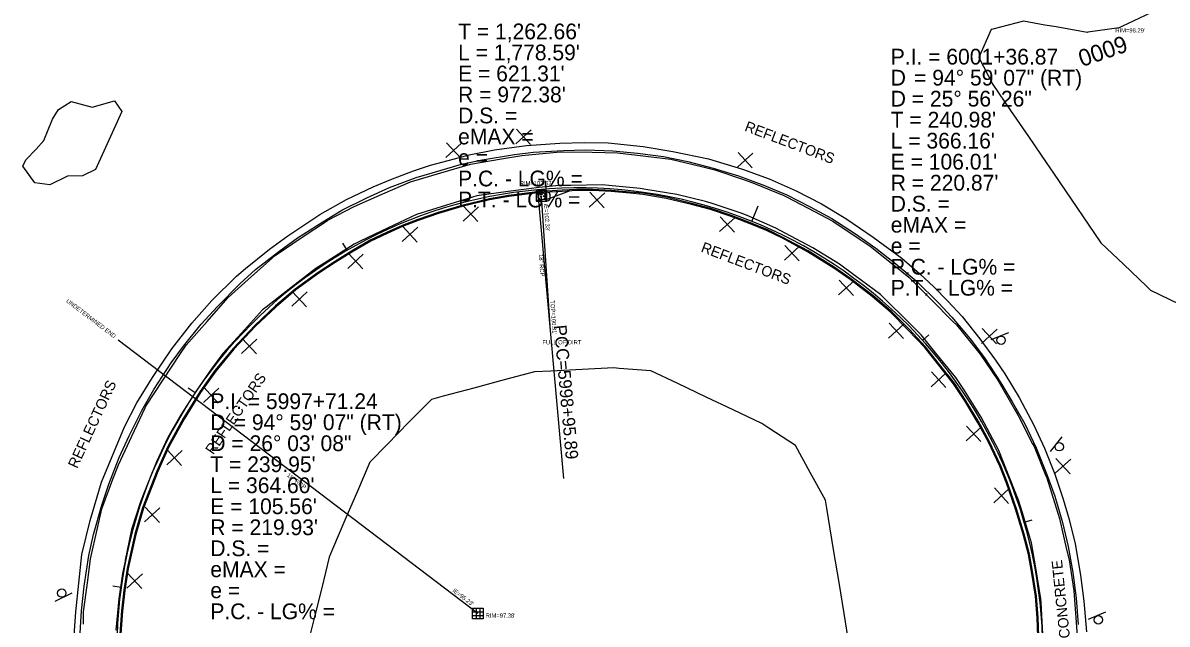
# Model space of a CAD drawing. Extents: x 2132221 to 2141942, y 535736 to 547298.
# Drawn here: x 2137783 to 2138328, y 541244 to 541530 of the extents above; entities that cross this region are included whole.
import ezdxf

# ---------------------------------------------------------------- set-up
doc = ezdxf.new("R2010")
doc.units = 0
for name, color, linetype in [('RD_EX_BldgApp', 7, 'Continuous'), ('RD_EX_Conc', 7, 'Continuous'), ('RD_EX_Conc_txCode', 7, 'Continuous'), ('RD_EX_DR_Inlet', 7, 'Continuous'), ('RD_EX_DR_Inlet_txCode', 7, 'Continuous'), ('RD_EX_DR_Pipe', 7, 'Continuous'), ('RD_EX_DR_Pipe_txCode', 7, 'Continuous'), ('RD_EX_Misc', 7, 'Continuous'), ('RD_EX_Misc_txCode', 7, 'Continuous'), ('RD_EX_Road', 7, 'Continuous'), ('RD_EX_VEG', 7, 'Continuous'), ('RD_HC_Cl', 7, 'Continuous'), ('RD_HC_Data', 7, 'Continuous'), ('RD_HC_Data_Tic', 7, 'Continuous'), ('RD_HC_TX_Sta50', 7, 'Continuous')]:
    doc.layers.add(name, color=color, linetype=linetype)

msp = doc.modelspace()

# ---------------------------------------------------------------- linework, layer by layer
at = {"layer": 'RD_EX_BldgApp'}
for p, q in [((2138252, 541382.29), (2138243.64, 541378.95)), ((2138277.45, 541332.87), (2138271.86, 541325.82)), ((2137798.11, 541254.6), (2137806.19, 541258.56)), ((2138298.3, 541249.27), (2138289.95, 541245.93))]:
    msp.add_line(p, q, dxfattribs=at)
for centre in [(2138248.55, 541378.74), (2138276.23, 541328.08), (2137801.27, 541258.41), (2138294.86, 541245.71)]:
    msp.add_circle(centre, 2, dxfattribs=at)
at = {"layer": 'RD_EX_Conc'}
for points in [[(2137809.9, 541236.85), (2137810.67, 541249.92), (2137811.95, 541261.74), (2137814.2, 541276.26), (2137816.38, 541286.36), (2137820.27, 541300.21), (2137823.71, 541310.23), (2137828.59, 541322.97), (2137833.35, 541333.32), (2137839.33, 541345.31), (2137845.09, 541355.38), (2137853.29, 541368.07), (2137859.2, 541376.01), (2137867.7, 541386.43), (2137875.36, 541394.83), (2137886.09, 541405.64), (2137893.56, 541412.39), (2137904.55, 541421.05), (2137913.48, 541427.47), (2137925.5, 541435.17), (2137934.61, 541440.69), (2137946.46, 541446.57), (2137957.3, 541451.42), (2137969.97, 541456.2), (2137977.71, 541458.51), (2137991.56, 541462.52), (2138001.45, 541464.69), (2138016.86, 541467.1), (2138025.89, 541468.29), (2138040.13, 541469.12), (2138050.68, 541469.39), (2138063.73, 541468.92), (2138075.37, 541467.85), (2138087.77, 541466.18), (2138099.44, 541463.88), (2138111.45, 541460.7), (2138123.51, 541457.09), (2138135.84, 541452.35), (2138146.49, 541447.92), (2138157.71, 541442.27), (2138168.03, 541436.64), (2138179.29, 541429.34), (2138188.86, 541422.57), (2138198.45, 541415.12), (2138208.06, 541407), (2138218.81, 541396.59), (2138225.15, 541389.7), (2138233.85, 541379.45), (2138240.63, 541370.47), (2138248.48, 541358.49), (2138253.84, 541349.5), (2138259.79, 541338.98), (2138265.22, 541327.61), (2138270.33, 541314.83), (2138274.13, 541304.53), (2138277.76, 541292.01), (2138280.52, 541280.67), (2138282.66, 541268.21), (2138284.27, 541256), (2138285.23, 541243.42)], [(2138266.21, 541233.45), (2138265.75, 541246.72), (2138264.91, 541256.96), (2138263.09, 541268.74), (2138261.59, 541276.8), (2138259, 541286.4), (2138255.34, 541298.3), (2138251.16, 541310.78), (2138247.93, 541318.86), (2138242.36, 541330.57), (2138237.34, 541339.78), (2138231.26, 541350), (2138225.91, 541358.07), (2138219.5, 541366.18), (2138212.24, 541375.32), (2138204.35, 541383.64), (2138195.79, 541392.27), (2138187.13, 541399.66), (2138176.72, 541407.64), (2138168.85, 541413.07), (2138156.38, 541420.83), (2138144.46, 541427.29), (2138136.89, 541431), (2138129.07, 541434.21), (2138120.06, 541437.71), (2138110.16, 541440.98), (2138101.08, 541443.44), (2138089.11, 541446.3), (2138077.92, 541448.2), (2138071.8, 541448.71), (2138062.92, 541449.51), (2138054.03, 541450.02), (2138046.57, 541450.04), (2138039.5, 541449.63), (2138027.76, 541448.9), (2138014.11, 541447.2), (2138004.99, 541445.55), (2137991.84, 541442.45), (2137980.69, 541439.03), (2137971, 541435.8), (2137963.49, 541432.9), (2137956.18, 541429.64), (2137948.4, 541425.98), (2137939.42, 541420.76), (2137931.46, 541415.74), (2137923.61, 541410.65), (2137912.77, 541402.73), (2137903.36, 541394.72), (2137893.52, 541385.46), (2137883.22, 541374.45), (2137874.63, 541364.03), (2137867.35, 541353.95), (2137859.48, 541341.2), (2137852.3, 541327.96), (2137846.98, 541316.31), (2137840.2, 541298.86), (2137836.48, 541286.28), (2137832.95, 541270.07), (2137831.34, 541259.71), (2137830.24, 541249.86), (2137829.46, 541239.05)], [(2138027.76, 541448.9), (2138028.08, 541445.6), (2138032.89, 541446.01), (2138043.03, 541449.83)]]:
    msp.add_lwpolyline(points, dxfattribs=at)
at = {"layer": 'RD_EX_DR_Inlet'}
for p, q in [((2138032.2, 541445.01), (2138032.2, 541450.01)), ((2137996.87, 541249.51), (2138001.87, 541249.51)), ((2137996.87, 541247.81), (2138001.87, 541247.81)), ((2137998.57, 541251.21), (2137998.57, 541246.21)), ((2138000.27, 541251.21), (2138000.27, 541246.21))]:
    msp.add_line(p, q, dxfattribs=at)
for points in [[(2138032.2, 541445.01), (2138032.2, 541450.01), (2138027.2, 541450.01), (2138027.2, 541445.01)], [(2137996.87, 541246.21), (2137996.87, 541251.21), (2138001.87, 541251.21), (2138001.87, 541246.21)]]:
    msp.add_lwpolyline(points, close=True, dxfattribs=at)
for centre, radius in [((2138029.92, 541447.39), 1.75), ((2138029.94, 541448.31), 0.175), ((2138029.38, 541447.01), 0.175), ((2138030.72, 541447.36), 0.175)]:
    msp.add_circle(centre, radius, dxfattribs=at)
at = {"layer": 'RD_EX_DR_Pipe'}
for p, q in [((2138029.61, 541447.47), (2138033.88, 541383.18)), ((2137999.4, 541248.65), (2137828.05, 541378.87))]:
    msp.add_line(p, q, dxfattribs=at)
at = {"layer": 'RD_EX_Misc'}
for p, q in [((2138017.45, 541472.18), (2138024.79, 541478.96)), ((2138017.73, 541479.25), (2138024.51, 541471.9)), ((2137984.21, 541465.72), (2137991.56, 541472.5)), ((2137984.5, 541472.78), (2137991.28, 541465.43)), ((2138122.99, 541461.07), (2138130.34, 541467.85)), ((2138123.28, 541468.13), (2138130.06, 541460.78)), ((2138052.45, 541442.12), (2138059.8, 541448.9)), ((2138052.74, 541449.18), (2138059.52, 541441.83)), ((2137992.34, 541435.5), (2137999.69, 541442.28)), ((2137992.63, 541442.57), (2137999.41, 541435.22)), ((2138114.82, 541437.54), (2138121.6, 541430.19)), ((2137963.43, 541425.8), (2137970.78, 541432.58)), ((2137963.72, 541432.87), (2137970.5, 541425.52)), ((2138114.54, 541430.47), (2138121.89, 541437.25)), ((2138145.36, 541416.86), (2138152.71, 541423.64)), ((2138145.64, 541423.92), (2138152.42, 541416.57)), ((2137937.5, 541412.97), (2137944.85, 541419.75)), ((2137937.79, 541420.03), (2137944.57, 541412.69)), ((2138171.19, 541400.31), (2138178.54, 541407.09)), ((2138171.48, 541407.38), (2138178.26, 541400.03)), ((2137910.74, 541394.97), (2137918.08, 541401.75)), ((2137911.02, 541402.04), (2137917.8, 541394.69)), ((2138195.01, 541379.83), (2138202.36, 541386.61)), ((2138195.29, 541386.9), (2138202.08, 541379.55)), ((2138239.29, 541377.27), (2138246.64, 541384.05)), ((2138239.57, 541384.34), (2138246.35, 541376.99)), ((2137886.87, 541372.52), (2137894.22, 541379.3)), ((2137887.15, 541379.58), (2137893.93, 541372.23)), ((2138215.2, 541356.61), (2138222.55, 541363.39)), ((2138215.49, 541363.68), (2138222.27, 541356.33)), ((2137868.74, 541349.16), (2137876.09, 541355.94)), ((2137869.02, 541356.22), (2137875.81, 541348.87)), ((2138231.87, 541330.84), (2138239.22, 541337.62)), ((2138232.15, 541337.9), (2138238.94, 541330.55)), ((2137851.27, 541319.46), (2137858.62, 541326.24)), ((2137851.55, 541326.52), (2137858.34, 541319.18)), ((2138274.37, 541315.44), (2138281.72, 541322.22)), ((2138274.65, 541322.51), (2138281.43, 541315.16)), ((2138245.06, 541301.4), (2138252.41, 541308.18)), ((2138245.35, 541308.46), (2138252.13, 541301.11)), ((2137840.67, 541292.3), (2137848.02, 541299.08)), ((2137840.95, 541299.36), (2137847.73, 541292.01)), ((2137832.28, 541260.83), (2137839.63, 541267.61)), ((2137832.56, 541267.9), (2137839.34, 541260.55))]:
    msp.add_line(p, q, dxfattribs=at)
for points in [[(2137811.6, 541243.61), (2137811.69, 541249.58), (2137813.61, 541264.45), (2137814.95, 541274.73), (2137818.25, 541289.36), (2137820.33, 541298.57), (2137825.64, 541312.6), (2137828.24, 541319.47), (2137834.63, 541333.04), (2137841.01, 541346.61), (2137841.35, 541347.32), (2137849.59, 541359.85), (2137857.84, 541372.38), (2137860.51, 541376.43), (2137870.44, 541387.68), (2137880.37, 541398.92), (2137880.5, 541399.07), (2137891.68, 541409.08), (2137902.88, 541419.12), (2137915.33, 541427.47), (2137927.79, 541435.83), (2137928.02, 541435.99), (2137940.44, 541442.49), (2137954.2, 541448.46), (2137967.37, 541454.16), (2137981.75, 541458.42), (2137995.83, 541462.58), (2138010.62, 541465.09), (2138020.29, 541466.73), (2138035.23, 541468.1), (2138038.87, 541468.44), (2138053.87, 541468.21), (2138065.83, 541468.03), (2138080.71, 541466.2), (2138091.28, 541464.91), (2138105.86, 541461.41), (2138112.22, 541459.88), (2138126.42, 541455.07), (2138131.2, 541453.45), (2138145.03, 541447.62), (2138146.39, 541447.04), (2138159.66, 541440.05), (2138168.48, 541435.41), (2138180.96, 541427.1), (2138186.27, 541423.57), (2138197.97, 541414.18), (2138204.6, 541408.86), (2138215.19, 541398.24), (2138225.78, 541387.61), (2138227.28, 541386.11), (2138236.74, 541374.46), (2138238.57, 541372.21), (2138246.94, 541359.76), (2138247.49, 541358.93), (2138254.99, 541345.94), (2138256.76, 541342.88), (2138263.57, 541329.51), (2138264.26, 541328.16), (2138269.92, 541314.26), (2138270.31, 541313.3), (2138274.81, 541298.99), (2138276.42, 541293.85), (2138279.76, 541279.23), (2138280.91, 541274.2), (2138283.25, 541259.47), (2138284.29, 541244.51), (2138284.92, 541235.38)], [(2138268.46, 541238.94), (2138267.65, 541253.92), (2138267.55, 541255.67), (2138265.09, 541270.46), (2138263.1, 541282.37), (2138258.68, 541296.7), (2138256.83, 541302.69), (2138251.3, 541316.63), (2138247.49, 541326.23), (2138240.52, 541339.51), (2138239.13, 541342.15), (2138231.05, 541354.79), (2138227.04, 541361.08), (2138217.53, 541372.69), (2138210.43, 541381.35), (2138199.8, 541391.94), (2138197.38, 541394.35), (2138191.14, 541400.57), (2138179.05, 541409.45), (2138171.57, 541414.96), (2138158.94, 541422.8), (2138145.67, 541429.8), (2138141.34, 541432.09), (2138127.58, 541438.07), (2138124.82, 541439.27), (2138110.56, 541443.94), (2138107.81, 541444.84), (2138094.16, 541448.2), (2138079.35, 541450.58), (2138076.68, 541451.01), (2138061.74, 541452.41), (2138058.72, 541452.69), (2138043.72, 541452.47), (2138038.18, 541452.39), (2138028.66, 541451.49), (2138013.8, 541449.49), (2137998.85, 541447.48), (2137984.51, 541443.08), (2137970.17, 541438.68), (2137956.63, 541432.21), (2137943.1, 541425.75), (2137940.43, 541424.48), (2137927.75, 541416.47), (2137922.23, 541412.98), (2137910.42, 541403.74), (2137898.6, 541394.5), (2137896.89, 541393.17), (2137886.81, 541382.06), (2137878.03, 541372.39), (2137872.61, 541365.18), (2137865.35, 541354.85), (2137857.99, 541343.32), (2137851.76, 541332.4), (2137846.39, 541320.96), (2137840.81, 541307.04), (2137838.71, 541301.8), (2137834.47, 541288.73), (2137831.48, 541274.03), (2137831.39, 541273.62), (2137830.19, 541267.72), (2137828.42, 541255.7), (2137826.99, 541240.76)]]:
    msp.add_lwpolyline(points, dxfattribs=at)
at = {"layer": 'RD_EX_Road'}
for points in [[(2137806.51, 541229.21), (2137807.92, 541249.52), (2137810.89, 541276.78), (2137814.71, 541292.97), (2137820.25, 541311.17), (2137831.13, 541337.48), (2137837.06, 541348.96), (2137844.54, 541361.08), (2137853.65, 541374.7), (2137863.26, 541386.97), (2137872.77, 541397.73), (2137884.52, 541409.29), (2137888.81, 541412.87), (2137900.19, 541422.16), (2137908.95, 541428.51), (2137924.2, 541438.58), (2137936.89, 541445.74), (2137949.55, 541451.85), (2137957.94, 541455.24), (2137968.81, 541459.41), (2137976.86, 541462.07), (2137988.28, 541465.19), (2137995.27, 541467.05), (2138007.28, 541469.32), (2138022.61, 541471.42), (2138038.36, 541472.55), (2138049.96, 541472.87), (2138061.39, 541472.77), (2138078.07, 541470.93), (2138092.26, 541468.54), (2138109.29, 541465.17), (2138125.39, 541460.25), (2138138.08, 541455.56), (2138151.04, 541449.87), (2138163.11, 541443.65), (2138174.61, 541436.79), (2138187.68, 541427.83), (2138201.29, 541417.85), (2138209.85, 541410.42), (2138216.45, 541404.16), (2138223.18, 541397.31), (2138229.96, 541390.05), (2138238.48, 541379.39), (2138245.89, 541369.24), (2138250.4, 541362.84), (2138257.09, 541351.57), (2138264.2, 541338.27), (2138269.27, 541327.4), (2138274.21, 541315.06), (2138278.1, 541303.1), (2138280.95, 541293.42), (2138283.87, 541281.82), (2138286.4, 541266.98), (2138288.03, 541254.55), (2138289.17, 541240.06)], [(2138266.72, 541233.46), (2138266.25, 541246.75), (2138265.41, 541257.02), (2138263.58, 541268.82), (2138262.07, 541276.91), (2138259.48, 541286.54), (2138255.82, 541298.45), (2138251.63, 541310.95), (2138248.38, 541319.06), (2138242.81, 541330.8), (2138237.78, 541340.03), (2138231.68, 541350.27), (2138226.31, 541358.36), (2138219.89, 541366.49), (2138212.62, 541375.65), (2138204.7, 541383.98), (2138196.13, 541392.64), (2138187.45, 541400.05), (2138177.02, 541408.05), (2138169.13, 541413.49), (2138156.64, 541421.26), (2138144.69, 541427.74), (2138137.09, 541431.45), (2138129.26, 541434.67), (2138120.23, 541438.18), (2138110.3, 541441.46), (2138101.21, 541443.93), (2138089.21, 541446.79), (2138077.98, 541448.7), (2138071.84, 541449.21), (2138062.96, 541450.01), (2138054.05, 541450.52), (2138046.56, 541450.54), (2138039.47, 541450.13), (2138027.72, 541449.4), (2138014.04, 541447.7), (2138004.89, 541446.04), (2137991.71, 541442.94), (2137980.54, 541439.51), (2137970.83, 541436.27), (2137963.3, 541433.36), (2137955.97, 541430.09), (2137948.16, 541426.42), (2137939.16, 541421.19), (2137931.19, 541416.16), (2137923.33, 541411.06), (2137912.46, 541403.13), (2137903.03, 541395.09), (2137893.16, 541385.82), (2137882.84, 541374.78), (2137874.23, 541364.34), (2137866.94, 541354.23), (2137859.05, 541341.45), (2137851.85, 541328.19), (2137846.52, 541316.5), (2137839.72, 541299.02), (2137835.99, 541286.4), (2137832.46, 541270.16), (2137830.85, 541259.78), (2137829.74, 541249.9), (2137828.96, 541239.07)]]:
    msp.add_lwpolyline(points, dxfattribs=at)
at = {"layer": 'RD_EX_VEG'}
for points in [[(2138328.18, 541534.3), (2138319.93, 541534.68), (2138306.38, 541528.25), (2138304.71, 541527.46), (2138289.85, 541525.38), (2138289.48, 541525.32), (2138274.7, 541527.89), (2138269.45, 541528.8), (2138259.2, 541530.58), (2138244.67, 541526.88), (2138243.81, 541526.66), (2138237.93, 541513.3), (2138244.61, 541500.47), (2138253.07, 541488.09), (2138261.54, 541475.7), (2138270, 541463.32), (2138273.46, 541458.25), (2138281.92, 541445.87), (2138290.38, 541433.48), (2138296.07, 541425.15), (2138306.93, 541414.81), (2138317.79, 541404.46), (2138319.66, 541402.67), (2138333.13, 541396.06)], [(2138176.25, 541233.85), (2138173.81, 541248.65), (2138171.37, 541263.45), (2138168.93, 541278.25), (2138167.97, 541284.08), (2138165.53, 541298.88), (2138164.9, 541302.68), (2138157.68, 541315.83), (2138150.61, 541328.71), (2138138.03, 541336.89), (2138134.58, 541339.13), (2138121.03, 541345.57), (2138108.14, 541351.69), (2138094.59, 541358.13), (2138081.7, 541364.25), (2138066.74, 541365.38), (2138064.07, 541365.59), (2138049.09, 541364.84), (2138034.1, 541364.1), (2138026.41, 541363.72), (2138011.91, 541359.85), (2137997.42, 541355.99), (2137982.92, 541352.13), (2137977.26, 541350.62), (2137966.75, 541339.92), (2137956.25, 541329.21), (2137947.88, 541320.69), (2137942.01, 541306.89), (2137936.13, 541293.09), (2137930.25, 541279.29), (2137928.65, 541275.53), (2137925.04, 541260.97), (2137921.42, 541246.42), (2137918.77, 541235.72)]]:
    msp.add_lwpolyline(points, dxfattribs=at)
msp.add_lwpolyline([(2137788.48, 541453.67), (2137782.75, 541461.68), (2137784.12, 541464.6), (2137789.03, 541469.69), (2137792.65, 541473.77), (2137796.81, 541484.07), (2137799.68, 541488.57), (2137805.78, 541492.36), (2137815.67, 541489.66), (2137826.45, 541492.78), (2137829.9, 541487.64), (2137826.01, 541479.25), (2137822.1, 541470.48), (2137817.27, 541460.1), (2137811.09, 541456.99), (2137803.98, 541456.89), (2137795.55, 541452.81)], close=True, dxfattribs=at)
at = {"layer": 'RD_HC_Cl'}
for centre, radius, start, end in [((2138047.44, 541231.33), 219.93, 95.1276, 190.1127), ((2138047.52, 541230.39), 220.87, 0.1424, 95.1276)]:
    msp.add_arc(centre, radius, start, end, dxfattribs=at)
at = {"layer": 'RD_HC_Data'}
msp.add_line((2138027.78, 541450.38), (2138040.11, 541313.03), dxfattribs=at)
at = {"layer": 'RD_HC_Data_Tic'}
for p, q in [((2138031.88, 541450.71), (2138031.59, 541454.7)), ((2138129.83, 541435.35), (2138132.81, 541442.78)), ((2137937.11, 541421.58), (2137935.1, 541425.04)), ((2138211.2, 541378.7), (2138214.16, 541381.38)), ((2137864.76, 541353.8), (2137861.44, 541356.02)), ((2138259.58, 541292.16), (2138263.42, 541293.28)), ((2137829.54, 541261.13), (2137825.58, 541261.67))]:
    msp.add_line(p, q, dxfattribs=at)

# ---------------------------------------------------------------- texts
at = {"layer": 'RD_EX_Conc_txCode'}
msp.add_text('CONCRETE', height=5, rotation=95.8919, dxfattribs=at).set_placement((2138281.38, 541237.11))
at = {"layer": 'RD_EX_DR_Inlet_txCode'}
for s, p in [("RIM=98.29'", (2138302.96, 541525.26)), ("RIM=107.63'", (2138019.36, 541452.52)), ('FULL OF DIRT', (2138030.14, 541376.81)), ("RIM=97.38'", (2138003.14, 541246.73))]:
    msp.add_text(s, height=2, dxfattribs=at).set_placement(p)
for s, rotation, p in [("IE=102.33'", 273.801, (2138030.85, 541443.82)), ('UNDETERMINED END', 322.7678, (2137803.15, 541397.07)), ("TOP=100.31'", 273.801, (2138033.92, 541397.68)), ("IE=95.23'", 322.7659, (2137987.15, 541259.22))]:
    msp.add_text(s, height=2, rotation=rotation, dxfattribs=at).set_placement(p)
at = {"layer": 'RD_EX_DR_Pipe_txCode'}
for rotation, p in [(273.801, (2138028.45, 541419.69)), (322.7678, (2137908.24, 541314.16))]:
    msp.add_text('18" RCP', height=2, rotation=rotation, dxfattribs=at).set_placement(p)
at = {"layer": 'RD_EX_Misc_txCode'}
for rotation, p in [(339.2251, (2138126.04, 541478.54)), (339.2251, (2138105.25, 541421)), (55.3875, (2137873.37, 541323.99)), (65.1629, (2137808.56, 541317.41))]:
    msp.add_text('REFLECTORS', height=5, rotation=rotation, dxfattribs=at).set_placement(p)
at = {"layer": 'RD_HC_Data'}
for s, p in [("T = 1,262.66'", (2137990, 541522)), ("L = 1,778.59'", (2137990, 541512)), ('P.I. = 6001+36.87', (2138196, 541510)), ("E = 621.31'", (2137990, 541502)), ('D', (2138196, 541500)), ('    = 94%%d 59\' 07" (RT)', (2138196, 541500)), ("R = 972.38'", (2137990, 541492)), ('D = 25%%d 56\' 26"', (2138196, 541490)), ('D.S. = ', (2137990, 541482)), ("T = 240.98'", (2138196, 541480)), ('eMAX = ', (2137990, 541472)), ("L = 366.16'", (2138196, 541470)), ('e = ', (2137990, 541462)), ("E = 106.01'", (2138196, 541460)), ('P.C. - LG% = ', (2137990, 541452)), ("R = 220.87'", (2138196, 541450)), ('P.T. - LG% = ', (2137990, 541442)), ('D.S. = ', (2138196, 541440)), ('eMAX = ', (2138196, 541430)), ('e = ', (2138196, 541420)), ('P.C. - LG% = ', (2138196, 541410)), ('P.T. - LG% = ', (2138196, 541400)), ('P.I. = 5997+71.24', (2137872, 541346)), ('D', (2137872, 541336)), ('    = 94%%d 59\' 07" (RT)', (2137872, 541336)), ('D = 26%%d 03\' 08"', (2137872, 541326)), ("T = 239.95'", (2137872, 541316)), ("L = 364.60'", (2137872, 541306)), ("E = 105.56'", (2137872, 541296)), ("R = 219.93'", (2137872, 541286)), ('D.S. = ', (2137872, 541276)), ('eMAX = ', (2137872, 541266)), ('e = ', (2137872, 541256)), ('P.C. - LG% = ', (2137872, 541246))]:
    msp.add_text(s, height=7.5, dxfattribs=at).set_placement(p)
msp.add_text('PCC=5998+95.89', height=6, rotation=275.1276, dxfattribs=at).set_placement((2138035.58, 541385.82))
at = {"layer": 'RD_HC_TX_Sta50'}
msp.add_text('6000', height=8, rotation=198.8142, dxfattribs=at).set_placement((2138306.98, 541524.03))

doc.saveas('drawing.dxf')
